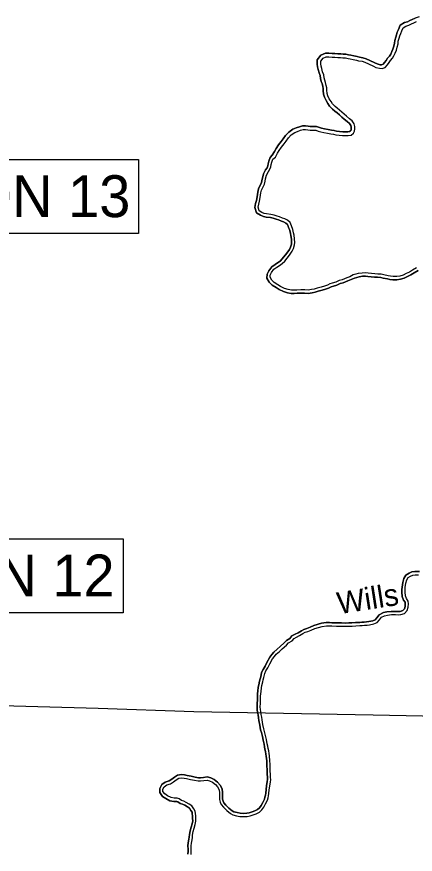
# Model space of a CAD drawing. Extents: x -12.1 to 34, y 0 to 22.
# Drawn here: x 6.799 to 8.417, y 13.792 to 17.192 of the extents above; entities that cross this region are included whole.
import ezdxf

# ---------------------------------------------------------------- set-up
doc = ezdxf.new("R2010")
doc.units = 0
for name, color, linetype in [('BR_P_Gen_Text', 7, 'Continuous'), ('GM_X_Major_River', 7, 'Continuous'), ('GM_X_Major_River_Text', 7, 'Continuous'), ('GM_X_Township', 7, 'Continuous')]:
    doc.layers.add(name, color=color, linetype=linetype)

msp = doc.modelspace()

# ---------------------------------------------------------------- linework, layer by layer
at = {"layer": 'BR_P_Gen_Text'}
for points in [[(5.7213, 16.6121), (7.293, 16.6121), (7.293, 16.3119), (5.7213, 16.3119)], [(5.6572, 15.0721), (7.2303, 15.0721), (7.2303, 14.7719), (5.6572, 14.7719)]]:
    msp.add_lwpolyline(points, close=True, dxfattribs=at)
at = {"layer": 'GM_X_Major_River'}
for points in [[(8.4168, 17.1867), (8.4047, 17.1815), (8.3952, 17.1763), (8.3858, 17.1716), (8.3728, 17.1682), (8.3564, 17.1581), (8.3485, 17.1405), (8.344, 17.1294), (8.3403, 17.1185), (8.3375, 17.1093), (8.3337, 17.0963), (8.3323, 17.0846), (8.3298, 17.0723), (8.3264, 17.0612), (8.3219, 17.0504), (8.3172, 17.0402), (8.3124, 17.0327), (8.3046, 17.0236), (8.2988, 17.0144), (8.2925, 17.0064), (8.2864, 16.9994), (8.2803, 16.9974), (8.2746, 16.9976), (8.2627, 17.0006), (8.2532, 17.0053), (8.2328, 17.0144), (8.2182, 17.0214), (8.2045, 17.0259), (8.1905, 17.0283), (8.1816, 17.031), (8.1673, 17.0335), (8.1558, 17.0363), (8.1463, 17.0377), (8.1347, 17.0396), (8.1243, 17.0399), (8.1151, 17.0411), (8.1032, 17.0422), (8.0906, 17.0425), (8.0797, 17.0431), (8.066, 17.0437), (8.0524, 17.0441), (8.0338, 17.0362), (8.0189, 17.0171), (8.0185, 16.9995), (8.0207, 16.9889), (8.023, 16.9782), (8.0266, 16.9643), (8.0309, 16.9534), (8.0319, 16.9418), (8.035, 16.9299), (8.0386, 16.9205), (8.0412, 16.9093), (8.0428, 16.9014), (8.0432, 16.893), (8.0445, 16.8782), (8.0478, 16.866), (8.0546, 16.8518), (8.0626, 16.8398), (8.069, 16.8295), (8.0813, 16.8165), (8.091, 16.8093), (8.0998, 16.802), (8.1096, 16.7934), (8.1189, 16.7849), (8.128, 16.777), (8.1401, 16.7664), (8.1496, 16.7593), (8.1548, 16.7512), (8.1569, 16.744), (8.157, 16.7383), (8.1561, 16.7321), (8.1546, 16.7287), (8.1506, 16.7257), (8.1434, 16.7246), (8.1322, 16.7248), (8.1228, 16.7254), (8.1093, 16.7267), (8.0974, 16.7279), (8.0883, 16.7299), (8.0763, 16.7319), (8.0632, 16.7343), (8.0491, 16.737), (8.0369, 16.7399), (8.0276, 16.7425), (8.0155, 16.7466), (8.0013, 16.7469), (7.9909, 16.7468), (7.9824, 16.7477), (7.9719, 16.7488), (7.9594, 16.7492), (7.9469, 16.7455), (7.934, 16.7409), (7.9202, 16.7358), (7.9034, 16.7233), (7.8906, 16.7099), (7.8802, 16.696), (7.8727, 16.6859), (7.861, 16.6717), (7.852, 16.6569), (7.8449, 16.6452), (7.8353, 16.6305)], [(7.8353, 16.6305), (7.8449, 16.6452), (7.852, 16.6569), (7.861, 16.6717), (7.8727, 16.6859), (7.8802, 16.696), (7.8906, 16.7099), (7.9034, 16.7233), (7.9202, 16.7358), (7.934, 16.7409), (7.9469, 16.7455), (7.9594, 16.7492), (7.9719, 16.7488), (7.9824, 16.7477), (7.9909, 16.7468), (8.0013, 16.7469), (8.0155, 16.7466), (8.0276, 16.7425), (8.0369, 16.7399), (8.0491, 16.737), (8.0632, 16.7343), (8.0763, 16.7319), (8.0883, 16.7299), (8.0974, 16.7279), (8.1093, 16.7267), (8.1228, 16.7254), (8.1322, 16.7248), (8.1434, 16.7246), (8.1506, 16.7257), (8.1546, 16.7287), (8.1561, 16.7321), (8.157, 16.7383), (8.1569, 16.744), (8.1548, 16.7512), (8.1496, 16.7593), (8.1401, 16.7664), (8.128, 16.777), (8.1189, 16.7849), (8.1096, 16.7934), (8.0998, 16.802), (8.091, 16.8093), (8.0813, 16.8165), (8.069, 16.8295), (8.0626, 16.8398), (8.0546, 16.8518), (8.0478, 16.866), (8.0445, 16.8782), (8.0432, 16.893), (8.0428, 16.9014), (8.0412, 16.9093), (8.0386, 16.9205), (8.035, 16.9299), (8.0319, 16.9418), (8.0309, 16.9534), (8.0266, 16.9643), (8.023, 16.9782), (8.0207, 16.9889), (8.0185, 16.9995), (8.0189, 17.0171), (8.0338, 17.0362), (8.0524, 17.0441), (8.066, 17.0437), (8.0797, 17.0431), (8.0906, 17.0425), (8.1032, 17.0422), (8.1151, 17.0411), (8.1243, 17.0399), (8.1347, 17.0396), (8.1463, 17.0377), (8.1558, 17.0363), (8.1673, 17.0335), (8.1816, 17.031), (8.1905, 17.0283), (8.2045, 17.0259), (8.2182, 17.0214), (8.2328, 17.0144), (8.2532, 17.0053), (8.2627, 17.0006), (8.2746, 16.9976), (8.2803, 16.9974), (8.2864, 16.9994), (8.2925, 17.0064), (8.2988, 17.0144), (8.3046, 17.0236), (8.3124, 17.0327), (8.3172, 17.0402), (8.3219, 17.0504), (8.3264, 17.0612), (8.3298, 17.0723), (8.3323, 17.0846), (8.3337, 17.0963), (8.3375, 17.1093), (8.3403, 17.1185), (8.344, 17.1294), (8.3485, 17.1405), (8.3564, 17.1581), (8.3728, 17.1682), (8.3858, 17.1716), (8.3952, 17.1763), (8.4047, 17.1815), (8.4163, 17.1865)], [(7.8493, 16.6225), (7.8578, 16.6377), (7.8648, 16.6492), (7.8732, 16.6631), (7.8844, 16.6767), (7.8922, 16.6871), (7.902, 16.7003), (7.9133, 16.7121), (7.9274, 16.7226), (7.939, 16.7269), (7.9514, 16.7313), (7.9614, 16.7342), (7.9709, 16.7339), (7.9809, 16.7329), (7.9901, 16.7319), (8.0011, 16.732), (8.0129, 16.7318), (8.0232, 16.7283), (8.0331, 16.7255), (8.046, 16.7224), (8.0605, 16.7197), (8.0737, 16.7173), (8.0854, 16.7153), (8.095, 16.7132), (8.1078, 16.7119), (8.1217, 16.7106), (8.1316, 16.7099), (8.1444, 16.7097), (8.1565, 16.7115), (8.1667, 16.7191), (8.1705, 16.728), (8.1719, 16.7373), (8.1718, 16.7462), (8.1685, 16.7575), (8.1606, 16.7695), (8.1495, 16.778), (8.1377, 16.7882), (8.1288, 16.796), (8.1195, 16.8044), (8.1095, 16.8133), (8.1002, 16.821), (8.0913, 16.8277), (8.0809, 16.8386), (8.0751, 16.8478), (8.0676, 16.8592), (8.0618, 16.8712), (8.0592, 16.8808), (8.0581, 16.894), (8.0576, 16.9032), (8.0558, 16.9124), (8.0528, 16.9249), (8.0492, 16.9344), (8.0466, 16.9444), (8.0455, 16.9568), (8.0408, 16.9689), (8.0375, 16.9817), (8.0353, 16.992), (8.0334, 17.0008), (8.0337, 17.0119), (8.0432, 17.024), (8.0552, 17.0291), (8.0655, 17.0288), (8.079, 17.0282), (8.09, 17.0276), (8.1024, 17.0273), (8.1134, 17.0264), (8.123, 17.025), (8.1333, 17.0247), (8.144, 17.023), (8.1529, 17.0217), (8.1643, 17.0189), (8.1781, 17.0165), (8.187, 17.0138), (8.2009, 17.0114), (8.2126, 17.0076), (8.2265, 17.0009), (8.2469, 16.9918), (8.2576, 16.9866), (8.2725, 16.9828), (8.2824, 16.9825), (8.2948, 16.9865), (8.304, 16.9969), (8.311, 17.0058), (8.3166, 17.0148), (8.3244, 17.0237), (8.3303, 17.033), (8.3355, 17.0444), (8.3404, 17.0562), (8.3442, 17.0687), (8.347, 17.0822), (8.3483, 17.0933), (8.3517, 17.105), (8.3545, 17.114), (8.358, 17.1243), (8.3622, 17.1346), (8.3681, 17.1478), (8.3787, 17.1543), (8.3911, 17.1576), (8.402, 17.1631), (8.4112, 17.1681), (8.4222, 17.1728)], [(8.4323, 17.1921), (8.4168, 17.1867)], [(7.9016, 16.3389), (7.8978, 16.3494), (7.8911, 16.3548), (7.882, 16.3599), (7.8735, 16.3624), (7.8612, 16.3674), (7.8526, 16.3703), (7.8402, 16.3739), (7.8287, 16.3765), (7.8112, 16.3788), (7.8002, 16.3809), (7.7884, 16.386), (7.7717, 16.3963), (7.7661, 16.4178), (7.7687, 16.434), (7.7721, 16.4468), (7.7744, 16.4607), (7.7771, 16.4795), (7.78, 16.4929), (7.7863, 16.5054), (7.7922, 16.5175), (7.7942, 16.5267), (7.796, 16.5368), (7.8003, 16.554), (7.8094, 16.5701), (7.8151, 16.5788), (7.8177, 16.5863), (7.8193, 16.5949), (7.822, 16.606), (7.8276, 16.6213), (7.8353, 16.6305)], [(7.8353, 16.6305), (7.8276, 16.6213), (7.822, 16.606), (7.8193, 16.5949), (7.8177, 16.5863), (7.8151, 16.5788), (7.8094, 16.5701), (7.8003, 16.554), (7.796, 16.5368), (7.7942, 16.5267), (7.7922, 16.5175), (7.7863, 16.5054), (7.78, 16.4929), (7.7771, 16.4795), (7.7744, 16.4607), (7.7721, 16.4468), (7.7687, 16.434), (7.7661, 16.4178), (7.7717, 16.3963), (7.7884, 16.386), (7.8002, 16.3809), (7.8112, 16.3788), (7.8287, 16.3765), (7.8402, 16.3739), (7.8526, 16.3703), (7.8612, 16.3674), (7.8735, 16.3624), (7.882, 16.3599), (7.8911, 16.3548), (7.8978, 16.3494), (7.9015, 16.339)], [(7.9138, 16.3434), (7.9088, 16.3572), (7.8985, 16.3657), (7.8871, 16.372), (7.8778, 16.3748), (7.8658, 16.3797), (7.8565, 16.3828), (7.8434, 16.3866), (7.831, 16.3894), (7.8132, 16.3917), (7.804, 16.3934), (7.7944, 16.3976), (7.783, 16.4046), (7.7794, 16.4185), (7.7814, 16.4313), (7.7849, 16.4441), (7.7873, 16.4587), (7.79, 16.4772), (7.7924, 16.4885), (7.798, 16.4996), (7.8046, 16.5131), (7.807, 16.5242), (7.8088, 16.5341), (7.8126, 16.5491), (7.8206, 16.5633), (7.8269, 16.573), (7.8304, 16.5829), (7.8321, 16.5922), (7.8345, 16.6022), (7.8387, 16.6136), (7.8493, 16.6225)], [(7.9015, 16.339), (7.9071, 16.3239), (7.9102, 16.3122), (7.9119, 16.3036), (7.914, 16.2894), (7.915, 16.2762), (7.9142, 16.2692), (7.9107, 16.2565), (7.9064, 16.2478), (7.8957, 16.2325), (7.8771, 16.2088), (7.8683, 16.2001), (7.8582, 16.1932), (7.8482, 16.1862), (7.834, 16.1771), (7.822, 16.1609), (7.8155, 16.1468), (7.8144, 16.1312), (7.8241, 16.1146), (7.836, 16.1024), (7.8525, 16.0925), (7.8637, 16.0851), (7.8817, 16.0767), (7.8981, 16.0716), (7.9134, 16.0693), (7.9256, 16.069), (7.9371, 16.0694), (7.9523, 16.0702), (7.9675, 16.07), (7.9828, 16.069), (7.9983, 16.0715), (8.0104, 16.0739), (8.0231, 16.0783), (8.039, 16.0823), (8.0524, 16.0861), (8.0651, 16.0907), (8.0755, 16.0951), (8.0844, 16.0985), (8.0985, 16.103), (8.1125, 16.109), (8.1239, 16.1122), (8.1439, 16.12), (8.1569, 16.125), (8.1697, 16.1315), (8.1791, 16.1341), (8.1886, 16.1368), (8.2024, 16.1388), (8.2151, 16.1389), (8.2247, 16.1376), (8.238, 16.1362), (8.2516, 16.1356), (8.2639, 16.1347), (8.2767, 16.1338), (8.2872, 16.1312), (8.3042, 16.1277), (8.314, 16.1259), (8.3264, 16.1244), (8.3427, 16.1241), (8.3573, 16.1263), (8.3721, 16.1313), (8.3862, 16.1377), (8.3995, 16.1439), (8.4129, 16.1528), (8.4289, 16.1618)], [(8.4289, 16.1618), (8.4129, 16.1528), (8.3995, 16.1439), (8.3862, 16.1377), (8.3721, 16.1313), (8.3573, 16.1263), (8.3427, 16.1241), (8.3264, 16.1244), (8.314, 16.1259), (8.3042, 16.1277), (8.2872, 16.1312), (8.2767, 16.1338), (8.2639, 16.1347), (8.2516, 16.1356), (8.238, 16.1362), (8.2247, 16.1376), (8.2151, 16.1389), (8.2024, 16.1388), (8.1886, 16.1368), (8.1791, 16.1341), (8.1697, 16.1315), (8.1569, 16.125), (8.1439, 16.12), (8.1239, 16.1122), (8.1125, 16.109), (8.0985, 16.103), (8.0844, 16.0985), (8.0755, 16.0951), (8.0651, 16.0907), (8.0524, 16.0861), (8.039, 16.0823), (8.0231, 16.0783), (8.0104, 16.0739), (7.9983, 16.0715), (7.9828, 16.069), (7.9675, 16.07), (7.9523, 16.0702), (7.9371, 16.0694), (7.9256, 16.069), (7.9134, 16.0693), (7.8981, 16.0716), (7.8817, 16.0767), (7.8637, 16.0851), (7.8525, 16.0925), (7.836, 16.1024), (7.8241, 16.1146), (7.8144, 16.1312), (7.8155, 16.1468), (7.822, 16.1609), (7.834, 16.1771), (7.8482, 16.1862), (7.8582, 16.1932), (7.8683, 16.2001), (7.8771, 16.2088), (7.8957, 16.2325), (7.9064, 16.2478), (7.9107, 16.2565), (7.9142, 16.2692), (7.915, 16.2762), (7.914, 16.2894), (7.9119, 16.3036), (7.9102, 16.3122), (7.9071, 16.3239), (7.9016, 16.3389)], [(8.4227, 16.1733), (8.4061, 16.164), (8.3931, 16.1553), (8.3807, 16.1496), (8.3673, 16.1434), (8.3542, 16.1391), (8.3418, 16.1372), (8.3273, 16.1375), (8.3159, 16.1388), (8.3067, 16.1405), (8.29, 16.1439), (8.2787, 16.1467), (8.2649, 16.1477), (8.2525, 16.1487), (8.239, 16.1493), (8.2262, 16.1506), (8.2159, 16.1519), (8.2014, 16.1518), (8.1858, 16.1496), (8.1756, 16.1467), (8.165, 16.1438), (8.1516, 16.1369), (8.1392, 16.1322), (8.1197, 16.1246), (8.1081, 16.1213), (8.0939, 16.1152), (8.0802, 16.1108), (8.0706, 16.1072), (8.0604, 16.1029), (8.0483, 16.0985), (8.0356, 16.0949), (8.0193, 16.0909), (8.007, 16.0865), (7.996, 16.0843), (7.9822, 16.0821), (7.968, 16.083), (7.9521, 16.0833), (7.9365, 16.0825), (7.9255, 16.082), (7.9145, 16.0823), (7.901, 16.0844), (7.8865, 16.0889), (7.8701, 16.0966), (7.8595, 16.1036), (7.8442, 16.1127), (7.8345, 16.1226), (7.8277, 16.1343), (7.8284, 16.1435), (7.8333, 16.1542), (7.8431, 16.1674), (7.8554, 16.1753), (7.8657, 16.1825), (7.8766, 16.19), (7.8868, 16.2001), (7.9061, 16.2247), (7.9177, 16.2411), (7.923, 16.2518), (7.9271, 16.2668), (7.9281, 16.276), (7.9269, 16.2909), (7.9247, 16.3058), (7.9229, 16.315), (7.9196, 16.3278), (7.9138, 16.3434)], [(7.7759, 14.4174), (7.7761, 14.4344), (7.7768, 14.4442), (7.7778, 14.4543), (7.7792, 14.4699), (7.7814, 14.4805), (7.785, 14.4947), (7.7873, 14.5038), (7.7894, 14.5128), (7.7931, 14.53), (7.7994, 14.5427), (7.8074, 14.5554), (7.8146, 14.5709), (7.8268, 14.5924), (7.8348, 14.6028), (7.8426, 14.6128), (7.8566, 14.6251), (7.8685, 14.6354), (7.8848, 14.6498), (7.8937, 14.6602), (7.9079, 14.6683), (7.9161, 14.6787), (7.9287, 14.6856), (7.9415, 14.6917), (7.9546, 14.6994), (7.9648, 14.7049), (7.9762, 14.7092), (7.9899, 14.7146), (8.0051, 14.7206), (8.0357, 14.7301), (8.0553, 14.7326), (8.0682, 14.7327), (8.0784, 14.7321), (8.098, 14.7315), (8.1171, 14.731), (8.1333, 14.7307), (8.1468, 14.7312), (8.1601, 14.7316), (8.1745, 14.7324), (8.1913, 14.7333), (8.2004, 14.7337), (8.2101, 14.7348), (8.2197, 14.7355), (8.2285, 14.7369), (8.2448, 14.7403), (8.2548, 14.7436), (8.2611, 14.7519), (8.2709, 14.7645), (8.2876, 14.7732), (8.3022, 14.7758), (8.3197, 14.7783), (8.3367, 14.778), (8.348, 14.7777), (8.3557, 14.7781), (8.3663, 14.7815), (8.3729, 14.7889), (8.3754, 14.7975), (8.3762, 14.8091), (8.3755, 14.8155), (8.3697, 14.8242), (8.3642, 14.8383), (8.3628, 14.8562), (8.3631, 14.8669), (8.3635, 14.8766), (8.3664, 14.8954), (8.3705, 14.9115), (8.3791, 14.9254), (8.3919, 14.9334), (8.4038, 14.9381), (8.4159, 14.9395), (8.4339, 14.9401)], [(8.4339, 14.9401), (8.4159, 14.9395), (8.4038, 14.9381), (8.3919, 14.9334), (8.3791, 14.9254), (8.3705, 14.9115), (8.3664, 14.8954), (8.3635, 14.8766), (8.3631, 14.8669), (8.3628, 14.8562), (8.3642, 14.8383), (8.3697, 14.8242), (8.3755, 14.8155), (8.3762, 14.8091), (8.3754, 14.7975), (8.3729, 14.7889), (8.3663, 14.7815), (8.3557, 14.7781), (8.348, 14.7777), (8.3367, 14.778), (8.3197, 14.7783), (8.3022, 14.7758), (8.2876, 14.7732), (8.2709, 14.7645), (8.2611, 14.7519), (8.2548, 14.7436), (8.2448, 14.7403), (8.2285, 14.7369), (8.2197, 14.7355), (8.2101, 14.7348), (8.2004, 14.7337), (8.1913, 14.7333), (8.1745, 14.7324), (8.1601, 14.7316), (8.1468, 14.7312), (8.1333, 14.7307), (8.1171, 14.731), (8.098, 14.7315), (8.0784, 14.7321), (8.0682, 14.7327), (8.0553, 14.7326), (8.0357, 14.7301), (8.0051, 14.7206), (7.9899, 14.7146), (7.9762, 14.7092), (7.9648, 14.7049), (7.9546, 14.6994), (7.9415, 14.6917), (7.9287, 14.6856), (7.9161, 14.6787), (7.9079, 14.6683), (7.8937, 14.6602), (7.8848, 14.6498), (7.8685, 14.6354), (7.8566, 14.6251), (7.8426, 14.6128), (7.8348, 14.6028), (7.8268, 14.5924), (7.8146, 14.5709), (7.8074, 14.5554), (7.7994, 14.5427), (7.7931, 14.53), (7.7894, 14.5128), (7.7873, 14.5038), (7.785, 14.4947), (7.7814, 14.4805), (7.7792, 14.4699), (7.7778, 14.4543), (7.7768, 14.4442), (7.7761, 14.4344), (7.7759, 14.4178)], [(7.7889, 14.4172), (7.7892, 14.4339), (7.7898, 14.4431), (7.7908, 14.4531), (7.7921, 14.468), (7.7942, 14.4776), (7.7976, 14.4915), (7.8, 14.5007), (7.8021, 14.51), (7.8055, 14.5256), (7.8108, 14.5363), (7.8188, 14.5492), (7.8262, 14.5649), (7.8377, 14.5852), (7.8451, 14.5948), (7.8521, 14.6038), (7.8652, 14.6152), (7.8772, 14.6256), (7.8941, 14.6406), (7.9021, 14.6499), (7.9166, 14.6582), (7.9247, 14.6686), (7.9346, 14.674), (7.9476, 14.6801), (7.9611, 14.688), (7.9702, 14.6931), (7.9808, 14.697), (7.9946, 14.7025), (8.0095, 14.7083), (8.0385, 14.7173), (8.0562, 14.7196), (8.0679, 14.7197), (8.0778, 14.719), (8.0976, 14.7185), (8.1168, 14.7179), (8.1334, 14.7177), (8.1472, 14.7181), (8.1607, 14.7186), (8.1752, 14.7194), (8.1919, 14.7202), (8.2014, 14.7206), (8.2113, 14.7218), (8.2213, 14.7226), (8.2308, 14.724), (8.2482, 14.7277), (8.2626, 14.7324), (8.2714, 14.7439), (8.2795, 14.7542), (8.2919, 14.7607), (8.3043, 14.7629), (8.3205, 14.7652), (8.3365, 14.7649), (8.3482, 14.7647), (8.3581, 14.7651), (8.3736, 14.7702), (8.3846, 14.7823), (8.3884, 14.7952), (8.3893, 14.8094), (8.3882, 14.82), (8.3814, 14.8303), (8.3771, 14.8413), (8.3759, 14.8565), (8.3762, 14.8665), (8.3765, 14.8754), (8.3792, 14.8928), (8.3827, 14.9063), (8.3886, 14.9159), (8.3978, 14.9217), (8.407, 14.9253), (8.4169, 14.9264), (8.4307, 14.9269)], [(7.4935, 13.7923), (7.4944, 13.8042), (7.4944, 13.8126), (7.4935, 13.8266), (7.4951, 13.8389), (7.4978, 13.8529), (7.4991, 13.8613), (7.4997, 13.8717), (7.5023, 13.8872), (7.5064, 13.9024), (7.5107, 13.9159), (7.5131, 13.928), (7.513, 13.9377), (7.5123, 13.9475), (7.5115, 13.9565), (7.5105, 13.963), (7.5062, 13.9699), (7.5003, 13.9793), (7.4919, 13.9844), (7.4808, 13.9914), (7.4724, 13.9952), (7.4617, 13.9985), (7.4531, 14.0052), (7.4483, 14.0063), (7.4362, 14.0062), (7.4207, 14.0096), (7.4042, 14.0182), (7.3912, 14.0272), (7.3794, 14.0425), (7.3793, 14.0594), (7.3875, 14.0751), (7.402, 14.0853), (7.4171, 14.0901), (7.4278, 14.0969), (7.4391, 14.1048), (7.4517, 14.1128), (7.4672, 14.1158), (7.4801, 14.1146), (7.4908, 14.1123), (7.5068, 14.1089), (7.5234, 14.1055), (7.5373, 14.1027), (7.5444, 14.1027), (7.5568, 14.1041), (7.5722, 14.1068), (7.5869, 14.1025), (7.6008, 14.0954), (7.6143, 14.085), (7.6246, 14.0727), (7.6329, 14.0577), (7.6348, 14.0427), (7.6346, 14.0163), (7.6366, 14.0076), (7.6396, 14.0006), (7.6472, 13.9917), (7.6599, 13.9798), (7.6735, 13.9686), (7.6809, 13.9647), (7.694, 13.9613), (7.7066, 13.9588), (7.7211, 13.958), (7.7328, 13.9584), (7.7432, 13.9606), (7.755, 13.964), (7.766, 13.9682), (7.7766, 13.9738), (7.7848, 13.9813), (7.7914, 13.9897), (7.7974, 14.002), (7.8043, 14.0164), (7.8066, 14.0239), (7.8085, 14.0325), (7.8101, 14.0405), (7.8113, 14.0554), (7.8134, 14.0705), (7.8161, 14.0874), (7.817, 14.095), (7.8166, 14.1049), (7.8158, 14.1168), (7.815, 14.1288), (7.8145, 14.1574), (7.814, 14.1708), (7.8122, 14.1898), (7.8108, 14.1986), (7.809, 14.2089), (7.8068, 14.2191), (7.805, 14.2289), (7.8028, 14.2385), (7.7995, 14.2557), (7.7966, 14.2708), (7.7921, 14.2869), (7.789, 14.2978), (7.7856, 14.3164), (7.7818, 14.3357), (7.7807, 14.3465), (7.7789, 14.3575), (7.777, 14.3686), (7.7755, 14.3791), (7.7746, 14.3894), (7.7749, 14.4057), (7.7759, 14.4182)], [(7.7759, 14.4178), (7.7749, 14.4057), (7.7746, 14.3894), (7.7755, 14.3791), (7.777, 14.3686), (7.7789, 14.3575), (7.7807, 14.3465), (7.7818, 14.3357), (7.7856, 14.3164), (7.789, 14.2978), (7.7921, 14.2869), (7.7966, 14.2708), (7.7995, 14.2557), (7.8028, 14.2385), (7.805, 14.2289), (7.8068, 14.2191), (7.809, 14.2089), (7.8108, 14.1986), (7.8122, 14.1898), (7.814, 14.1708), (7.8145, 14.1574), (7.815, 14.1288), (7.8158, 14.1168), (7.8166, 14.1049), (7.817, 14.095), (7.8161, 14.0874), (7.8134, 14.0705), (7.8113, 14.0554), (7.8101, 14.0405), (7.8085, 14.0325), (7.8066, 14.0239), (7.8043, 14.0164), (7.7974, 14.002), (7.7914, 13.9897), (7.7848, 13.9813), (7.7766, 13.9738), (7.766, 13.9682), (7.755, 13.964), (7.7432, 13.9606), (7.7328, 13.9584), (7.7211, 13.958), (7.7066, 13.9588), (7.694, 13.9613), (7.6809, 13.9647), (7.6735, 13.9686), (7.6599, 13.9798), (7.6472, 13.9917), (7.6396, 14.0006), (7.6366, 14.0076), (7.6346, 14.0163), (7.6348, 14.0427), (7.6329, 14.0577), (7.6246, 14.0727), (7.6143, 14.085), (7.6008, 14.0954), (7.5869, 14.1025), (7.5722, 14.1068), (7.5568, 14.1041), (7.5444, 14.1027), (7.5373, 14.1027), (7.5234, 14.1055), (7.5068, 14.1089), (7.4908, 14.1123), (7.4801, 14.1146), (7.4672, 14.1158), (7.4517, 14.1128), (7.4391, 14.1048), (7.4278, 14.0969), (7.4171, 14.0901), (7.402, 14.0853), (7.3875, 14.0751), (7.3793, 14.0594), (7.3794, 14.0425), (7.3912, 14.0272), (7.4042, 14.0182), (7.4207, 14.0096), (7.4362, 14.0062), (7.4483, 14.0063), (7.4531, 14.0052), (7.4617, 13.9985), (7.4724, 13.9952), (7.4808, 13.9914), (7.4919, 13.9844), (7.5003, 13.9793), (7.5062, 13.9699), (7.5105, 13.963), (7.5115, 13.9565), (7.5123, 13.9475), (7.513, 13.9377), (7.5131, 13.928), (7.5107, 13.9159), (7.5064, 13.9024), (7.5023, 13.8872), (7.4997, 13.8717), (7.4991, 13.8613), (7.4978, 13.8529), (7.4951, 13.8389), (7.4935, 13.8266), (7.4944, 13.8126), (7.4944, 13.8042), (7.4935, 13.792)], [(7.5065, 13.7913), (7.5075, 13.8038), (7.5074, 13.813), (7.5066, 13.8261), (7.508, 13.8368), (7.5107, 13.8507), (7.5121, 13.8599), (7.5127, 13.8702), (7.5151, 13.8845), (7.5189, 13.8987), (7.5234, 13.9126), (7.5261, 13.9268), (7.5261, 13.9382), (7.5253, 13.9485), (7.5245, 13.9581), (7.523, 13.9677), (7.5173, 13.9768), (7.5098, 13.9889), (7.4987, 13.9955), (7.487, 14.0029), (7.477, 14.0075), (7.4678, 14.0103), (7.4589, 14.0173), (7.4497, 14.0194), (7.4376, 14.0193), (7.4252, 14.022), (7.411, 14.0294), (7.4003, 14.0368), (7.3924, 14.047), (7.3924, 14.0563), (7.3976, 14.0662), (7.4079, 14.0734), (7.4227, 14.0781), (7.435, 14.086), (7.4463, 14.0939), (7.4566, 14.1004), (7.4679, 14.1026), (7.4782, 14.1016), (7.4881, 14.0996), (7.5041, 14.0961), (7.5208, 14.0927), (7.536, 14.0896), (7.5452, 14.0897), (7.5587, 14.0912), (7.5714, 14.0934), (7.5821, 14.0903), (7.5938, 14.0843), (7.6052, 14.0755), (7.6138, 14.0653), (7.6202, 14.0536), (7.6217, 14.0419), (7.6216, 14.0149), (7.6241, 14.0035), (7.6284, 13.9936), (7.6377, 13.9827), (7.6513, 13.97), (7.6662, 13.9577), (7.6762, 13.9524), (7.6911, 13.9486), (7.7049, 13.9458), (7.7209, 13.9449), (7.7344, 13.9453), (7.7464, 13.9479), (7.7591, 13.9516), (7.7715, 13.9563), (7.7842, 13.9631), (7.7944, 13.9724), (7.8025, 13.9828), (7.8091, 13.9963), (7.8165, 14.0117), (7.8192, 14.0206), (7.8213, 14.0298), (7.823, 14.0387), (7.8243, 14.054), (7.8263, 14.0686), (7.8291, 14.0856), (7.8301, 14.0945), (7.8296, 14.1055), (7.8288, 14.1176), (7.8281, 14.1293), (7.8275, 14.1577), (7.8271, 14.1716), (7.8252, 14.1915), (7.8237, 14.2007), (7.8218, 14.2114), (7.8196, 14.2216), (7.8178, 14.2316), (7.8156, 14.2411), (7.8123, 14.2582), (7.8094, 14.2738), (7.8046, 14.2905), (7.8017, 14.3007), (7.7984, 14.3188), (7.7948, 14.3376), (7.7936, 14.3483), (7.7918, 14.3596), (7.7899, 14.3706), (7.7884, 14.3806), (7.7877, 14.3898), (7.7879, 14.4051), (7.7889, 14.4172)]]:
    msp.add_lwpolyline(points, dxfattribs=at)
at = {"layer": 'GM_X_Township'}
msp.add_lwpolyline([(6.197, 14.4116), (7.1288, 14.3854), (7.5178, 14.3711), (8.2463, 14.358), (8.7133, 14.3482), (9.0604, 14.3404), (9.4725, 14.3272), (9.4839, 14.3266), (10.0713, 14.2961), (10.0724, 14.2962), (10.0768, 14.2965), (10.0818, 14.2967), (10.0892, 14.2969), (10.096, 14.2968), (10.1031, 14.2966), (10.1119, 14.2962), (10.1188, 14.2959), (10.1245, 14.2955), (10.5897, 14.2829)], dxfattribs=at)

# ---------------------------------------------------------------- texts
at = {"layer": 'BR_P_Gen_Text'}
for s, p in [('LOCATION 13', (5.782, 16.3787)), ('LOCATION 12', (5.7179, 14.8387))]:
    msp.add_text(s, height=0.17, dxfattribs=at).set_placement(p)
at = {"layer": 'GM_X_Major_River_Text'}
msp.add_text('Wills', height=0.08878, rotation=8.8402, dxfattribs=at).set_placement((8.1069, 14.7665))

doc.saveas('drawing.dxf')
